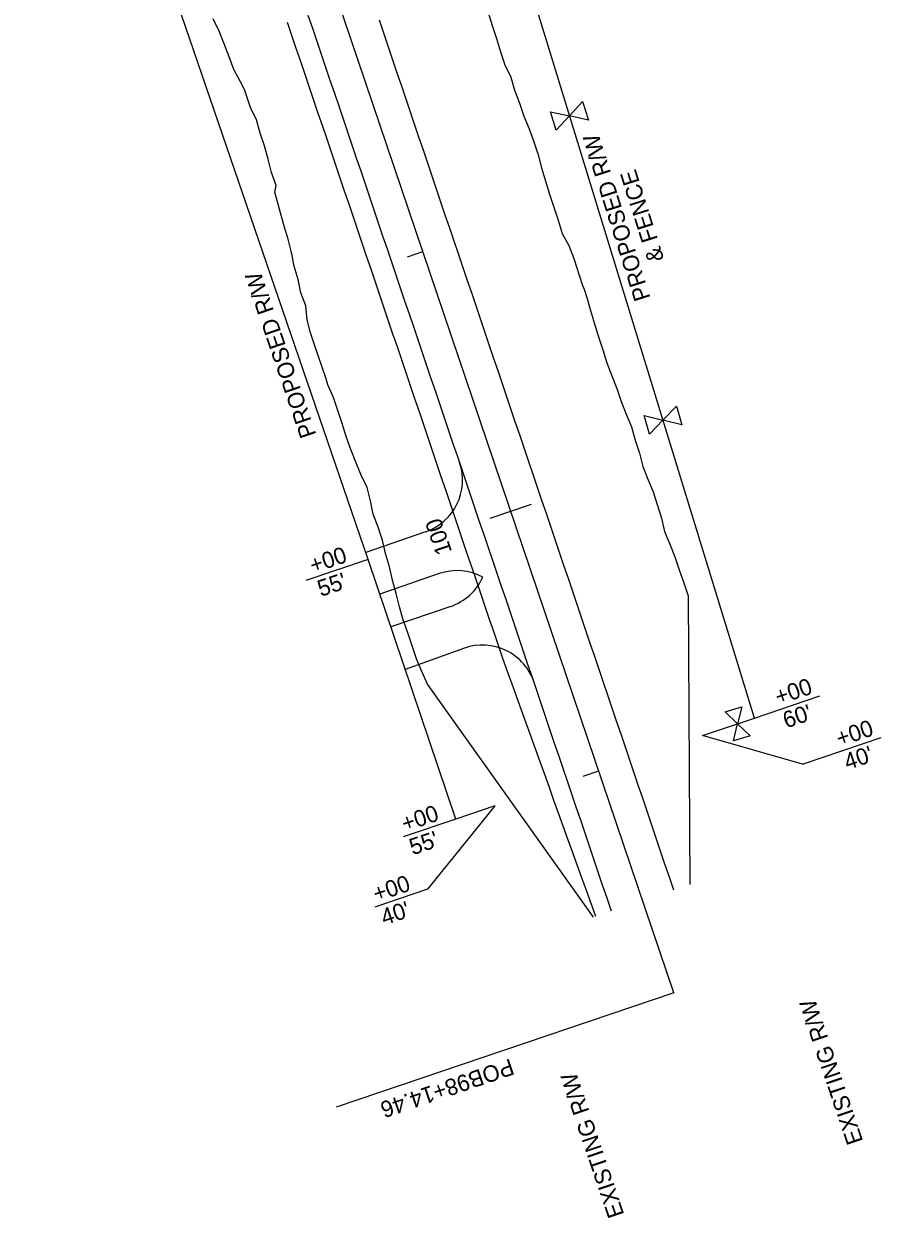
# Model space of a CAD drawing. Extents: x 634057 to 641016, y 287858 to 292331.
# Drawn here: x 634208.8 to 634521.5, y 288628.7 to 289064.4 of the extents above; entities that cross this region are included whole.
import ezdxf

# ---------------------------------------------------------------- set-up
doc = ezdxf.new("R2010")
doc.units = 0
for name, color, linetype in [('53', 7, 'Continuous'), ('R_50 Horz Alg PC PI PT', 7, 'Continuous'), ('R_50 Horz Alg Stations', 7, 'Continuous'), ('R_50 Horz Alg Ticks', 7, 'Continuous'), ('R_Drive', 7, 'Continuous'), ('R_Horz Alg', 7, 'Continuous'), ('R_No Plot', 7, 'Continuous'), ('R_Proposed Const Limits', 7, 'Continuous'), ('R_Proposed Road', 7, 'Continuous'), ('R_Proposed Shoulder', 7, 'Continuous'), ('R_ROW', 7, 'Continuous')]:
    doc.layers.add(name, color=color, linetype=linetype)

msp = doc.modelspace()

# ---------------------------------------------------------------- linework, layer by layer
at = {"layer": '53'}
for points in [[(634334.33, 288869.02), (634311.59, 288861.33)], [(634475.31, 288811.16), (634499.19, 288819.24)], [(634492.89, 288794.36), (634456.37, 288804.75)], [(634492.89, 288794.36), (634521.51, 288804.04)], [(634380.59, 288779.11), (634356.01, 288748.69)], [(634366.38, 288774.3), (634347.16, 288767.79)], [(634356.01, 288748.69), (634336.79, 288742.19)]]:
    msp.add_lwpolyline(points, dxfattribs=at)
at = {"layer": 'R_50 Horz Alg PC PI PT'}
msp.add_lwpolyline([(634445.9, 288710.9), (634322.76, 288669.23)], dxfattribs=at)
at = {"layer": 'R_50 Horz Alg Ticks'}
for points in [[(634348.69, 288979.45), (634354.37, 288981.38)], [(634378.85, 288884.09), (634394, 288889.22)], [(634412.79, 288790.01), (634418.48, 288791.93)]]:
    msp.add_lwpolyline(points, dxfattribs=at)
at = {"layer": 'R_Drive'}
for p, q in [((634355.31, 288879.08), (634333.57, 288871.61)), ((634360.29, 288863.87), (634338.59, 288856.42)), ((634364.52, 288851.92), (634342.66, 288844.41)), ((634369.49, 288836.71), (634347.9, 288828.91))]:
    msp.add_line(p, q, dxfattribs=at)
for centre, start, end in [((634348.82, 288897.99), 288.9589, 18.7206), ((634366.79, 288844.96), 61.8154, 108.9589), ((634358.02, 288870.84), 288.9673, 335.6258), ((634375.99, 288817.8), 18.7206, 108.9673)]:
    msp.add_arc(centre, 20, start, end, dxfattribs=at)
at = {"layer": 'R_Horz Alg'}
msp.add_line((634445.9, 288710.9), (634307.4, 289120.18), dxfattribs=at)
at = {"layer": 'R_Proposed Const Limits'}
for points in [[(634378.19, 289068.61), (634379.61, 289063.81), (634381.16, 289059.06), (634382.61, 289054.27), (634384.24, 289049.54), (634386.44, 289045.01), (634387.83, 289040.2), (634389.65, 289035.54), (634391.23, 289030.8), (634393.15, 289026.17), (634394.84, 289021.46), (634396.4, 289016.71), (634397.67, 289011.86), (634399.02, 289007.04), (634400.59, 289002.29), (634402.1, 288997.53), (634403.71, 288992.79), (634405.13, 288988), (634407.59, 288983.55), (634409.38, 288978.88), (634412.5, 288969.38), (634413.32, 288967.31), (634413.33, 288967.3), (634414.11, 288964.64), (634415.54, 288959.85), (634416.99, 288955.06), (634418.47, 288950.28), (634419.99, 288945.52), (634421.49, 288940.75), (634423.24, 288936.06), (634425.11, 288931.42), (634426.7, 288926.67), (634428.56, 288922.02), (634430.45, 288917.39), (634431.73, 288912.54), (634433.43, 288907.84), (634434.62, 288902.96), (634436.47, 288898.31), (634438.33, 288893.66), (634441.35, 288884.12), (634442.53, 288879.24), (634444.39, 288874.6), (634446.3, 288869.96), (634447.84, 288865.21), (634449.49, 288860.49), (634451.11, 288855.76)], [(634356.03, 288823.58), (634353.98, 288828.17), (634352.02, 288832.78), (634350.47, 288837.54), (634348.89, 288842.28), (634347.17, 288846.98), (634345.83, 288851.8), (634344.56, 288856.65), (634343.28, 288861.5), (634342.16, 288866.4), (634340.71, 288871.18), (634339.65, 288876.1), (634338.01, 288880.83), (634336.24, 288885.51), (634335.22, 288890.44), (634334.02, 288895.31), (634331.8, 288899.84), (634329.92, 288904.48), (634328.1, 288909.15), (634326.42, 288913.85), (634324.9, 288918.62), (634323.34, 288923.37), (634321.75, 288928.11), (634319.73, 288932.7), (634318.89, 288935.34), (634318.89, 288935.35), (634314.94, 288946.92), (634313.35, 288951.66), (634312.11, 288956.52), (634311.6, 288961.62), (634309.86, 288966.31), (634308.8, 288971.23), (634307.37, 288976.03), (634306.42, 288980.98), (634305.24, 288985.86), (634303.79, 288990.65), (634300.3, 289003.04), (634300.87, 289005.5), (634299.17, 289010.2), (634297.87, 289015.04), (634296.62, 289019.9), (634294.99, 289024.62), (634293.68, 289029.46), (634291.45, 289033.98), (634289.88, 289038.73), (634289.55, 289039.76), (634289.61, 289039.79), (634287.78, 289043.3), (634285.37, 289047.76), (634283.68, 289052.47), (634281.85, 289057.13), (634280, 289061.78), (634277.81, 289066.32)], [(634451.11, 288855.76), (634451.77, 288750.41)], [(634416.63, 288738.52), (634356.03, 288823.58)]]:
    msp.add_lwpolyline(points, dxfattribs=at)
at = {"layer": 'R_Proposed Road'}
for points in [[(634423.14, 288740.72), (634421.53, 288745.46), (634419.93, 288750.19), (634418.33, 288754.93), (634416.73, 288759.66), (634415.12, 288764.4), (634413.52, 288769.14), (634411.92, 288773.87), (634410.32, 288778.61), (634408.71, 288783.35), (634407.11, 288788.08), (634405.51, 288792.82), (634403.91, 288797.55), (634402.3, 288802.29), (634400.7, 288807.03), (634399.1, 288811.76), (634397.49, 288816.5), (634395.89, 288821.24), (634394.29, 288825.97), (634392.69, 288830.71), (634391.08, 288835.44), (634389.48, 288840.18), (634387.88, 288844.92), (634386.28, 288849.65), (634384.67, 288854.39), (634383.07, 288859.12), (634381.47, 288863.86), (634379.87, 288868.6), (634378.26, 288873.33), (634376.66, 288878.07), (634375.06, 288882.81), (634373.45, 288887.54), (634371.85, 288892.28), (634370.25, 288897.01), (634368.65, 288901.75), (634367.04, 288906.49), (634365.44, 288911.22), (634363.84, 288915.96), (634362.24, 288920.7), (634360.63, 288925.43), (634359.03, 288930.17), (634357.43, 288934.9), (634355.83, 288939.64), (634354.22, 288944.38), (634352.62, 288949.11), (634351.02, 288953.85), (634349.42, 288958.58), (634347.81, 288963.32), (634346.21, 288968.06), (634344.61, 288972.79), (634343, 288977.53), (634341.4, 288982.27), (634339.8, 288987), (634338.2, 288991.74), (634336.59, 288996.47), (634334.99, 289001.21), (634333.39, 289005.95), (634331.79, 289010.68), (634330.18, 289015.42), (634328.58, 289020.16), (634326.98, 289024.89), (634325.38, 289029.63), (634323.77, 289034.36), (634322.17, 289039.1), (634320.57, 289043.84), (634318.96, 289048.57), (634317.36, 289053.31), (634315.76, 289058.04), (634314.16, 289062.78), (634312.55, 289067.52)], [(634445.87, 288748.41), (634444.27, 288753.15), (634442.67, 288757.89), (634441.06, 288762.62), (634439.46, 288767.36), (634437.86, 288772.09), (634436.25, 288776.83), (634434.65, 288781.57), (634433.05, 288786.3), (634431.45, 288791.04), (634429.84, 288795.77), (634428.24, 288800.51), (634426.64, 288805.25), (634425.04, 288809.98), (634423.43, 288814.72), (634421.83, 288819.46), (634420.23, 288824.19), (634418.63, 288828.93), (634417.02, 288833.66), (634415.42, 288838.4), (634413.82, 288843.14), (634412.22, 288847.87), (634410.61, 288852.61), (634409.01, 288857.35), (634407.41, 288862.08), (634405.8, 288866.82), (634404.2, 288871.55), (634402.6, 288876.29), (634401, 288881.03), (634399.39, 288885.76), (634397.79, 288890.5), (634396.19, 288895.23), (634394.59, 288899.97), (634392.98, 288904.71), (634391.38, 288909.44), (634389.78, 288914.18), (634388.18, 288918.92), (634386.57, 288923.65), (634384.97, 288928.39), (634383.37, 288933.12), (634381.76, 288937.86), (634380.16, 288942.6), (634378.56, 288947.33), (634376.96, 288952.07), (634375.35, 288956.81), (634373.75, 288961.54), (634372.15, 288966.28), (634370.55, 288971.01), (634368.94, 288975.75), (634367.34, 288980.49), (634365.74, 288985.22), (634364.14, 288989.96), (634362.53, 288994.69), (634360.93, 288999.43), (634359.33, 289004.17), (634357.73, 289008.9), (634356.12, 289013.64), (634354.52, 289018.38), (634352.92, 289023.11), (634351.31, 289027.85), (634349.71, 289032.58), (634348.11, 289037.32), (634346.51, 289042.06), (634344.9, 289046.79), (634343.3, 289051.53), (634341.7, 289056.27), (634340.1, 289061), (634338.49, 289065.74)]]:
    msp.add_lwpolyline(points, dxfattribs=at)
at = {"layer": 'R_Proposed Shoulder'}
msp.add_lwpolyline([(634417.45, 288738.8), (634415.76, 288743.5), (634414.06, 288748.21), (634412.36, 288752.91), (634410.66, 288757.61), (634408.97, 288762.32), (634407.27, 288767.02), (634405.57, 288771.73), (634403.87, 288776.43), (634402.18, 288781.13), (634400.48, 288785.84), (634398.78, 288790.54), (634397.09, 288795.25), (634395.39, 288799.95), (634393.69, 288804.65), (634391.99, 288809.36), (634390.3, 288814.06), (634388.6, 288818.77), (634386.9, 288823.47), (634385.2, 288828.18), (634383.51, 288832.88), (634381.9, 288837.62), (634380.3, 288842.35), (634378.7, 288847.09), (634377.1, 288851.82), (634375.49, 288856.56), (634373.89, 288861.3), (634372.29, 288866.03), (634370.68, 288870.77), (634369.08, 288875.51), (634367.48, 288880.24), (634365.88, 288884.98), (634364.27, 288889.71), (634362.67, 288894.45), (634361.07, 288899.19), (634359.47, 288903.92), (634357.86, 288908.66), (634356.26, 288913.39), (634354.66, 288918.13), (634353.06, 288922.87), (634351.45, 288927.6), (634349.85, 288932.34), (634348.25, 288937.08), (634346.65, 288941.81), (634345.04, 288946.55), (634343.44, 288951.28), (634341.84, 288956.02), (634340.23, 288960.76), (634338.63, 288965.49), (634337.03, 288970.23), (634335.43, 288974.97), (634333.82, 288979.7), (634332.22, 288984.44), (634330.62, 288989.17), (634329.02, 288993.91), (634327.41, 288998.65), (634325.81, 289003.38), (634324.21, 289008.12), (634322.61, 289012.86), (634321, 289017.59), (634319.4, 289022.33), (634317.8, 289027.06), (634316.19, 289031.8), (634314.59, 289036.54), (634312.99, 289041.27), (634311.39, 289046.01), (634309.78, 289050.74), (634308.18, 289055.48), (634306.58, 289060.22), (634304.98, 289064.95)], dxfattribs=at)
at = {"layer": 'R_ROW'}
for p, q in [((634407.8, 289030.89), (634412.57, 289036.11)), ((634412.57, 289036.11), (634414.71, 289029.36)), ((634400.9, 289032.41), (634407.8, 289030.89)), ((634403.03, 289025.67), (634400.9, 289032.41)), ((634407.8, 289030.89), (634403.03, 289025.67)), ((634414.71, 289029.36), (634407.8, 289030.89)), ((634441.94, 288919.84), (634446.84, 288924.94)), ((634446.84, 288924.94), (634448.81, 288918.15)), ((634435.08, 288921.52), (634441.94, 288919.84)), ((634437.05, 288914.73), (634435.08, 288921.52)), ((634441.94, 288919.84), (634437.05, 288914.73)), ((634448.81, 288918.15), (634441.94, 288919.84)), ((634464.59, 288813.49), (634470.7, 288815.26)), ((634470.7, 288815.26), (634469.18, 288809.09)), ((634469.18, 288809.09), (634464.59, 288813.49)), ((634467.66, 288802.91), (634469.18, 288809.09)), ((634469.18, 288809.09), (634473.78, 288804.68)), ((634473.78, 288804.68), (634467.66, 288802.91))]:
    msp.add_line(p, q, dxfattribs=at)
for points in [[(634334.33, 288869.02), (634208.8, 289235.73)], [(634475.31, 288811.16), (634372.67, 289145.69)], [(634366.38, 288774.3), (634334.33, 288869.02)], [(634456.37, 288804.75), (634475.31, 288811.16)], [(634380.59, 288779.11), (634366.38, 288774.3)]]:
    msp.add_lwpolyline(points, dxfattribs=at)

# ---------------------------------------------------------------- texts
at = {"layer": '53'}
for s, rotation, p in [('PROPOSED R/W', 107.5755, (634437.44, 288964.45)), ('& FENCE', 107.5755, (634442.4, 288978.59)), ('PROPOSED R/W', 108.8966, (634315.56, 288914.59)), ('+00 ', 18.695, (634314.24, 288863.87)), ("55'  ", 18.695, (634317.12, 288855.35)), ('+00 ', 18.695, (634484.01, 288815.88)), ("60'  ", 18.695, (634486.9, 288807.35)), ('+00 ', 18.695, (634506.33, 288800.68)), ("40'  ", 18.695, (634509.21, 288792.15)), ('+00 ', 18.695, (634347.75, 288769.6)), ("55'  ", 18.695, (634350.63, 288761.08)), ('+00 ', 18.695, (634337.38, 288744)), ("40'  ", 18.695, (634340.26, 288735.47)), ('EXISTING R/W', 108.695, (634515.01, 288656.76)), ('EXISTING R/W', 108.695, (634427.87, 288630.01))]:
    msp.add_text(s, height=6, rotation=rotation, dxfattribs=at).set_placement(p)
at = {"layer": 'R_50 Horz Alg PC PI PT'}
msp.add_text('POB98+14.46', height=6, rotation=198.695, dxfattribs=at).set_placement((634386.28, 288687.03))
at = {"layer": 'R_50 Horz Alg Stations'}
msp.add_text('100', height=6, rotation=108.695, dxfattribs=at).set_placement((634365.03, 288871.88))
at = {"layer": 'R_No Plot'}
msp.add_text('+', height=0.1, rotation=108.695, dxfattribs=at).set_placement((634367.52, 288919.04))

doc.saveas('drawing.dxf')
